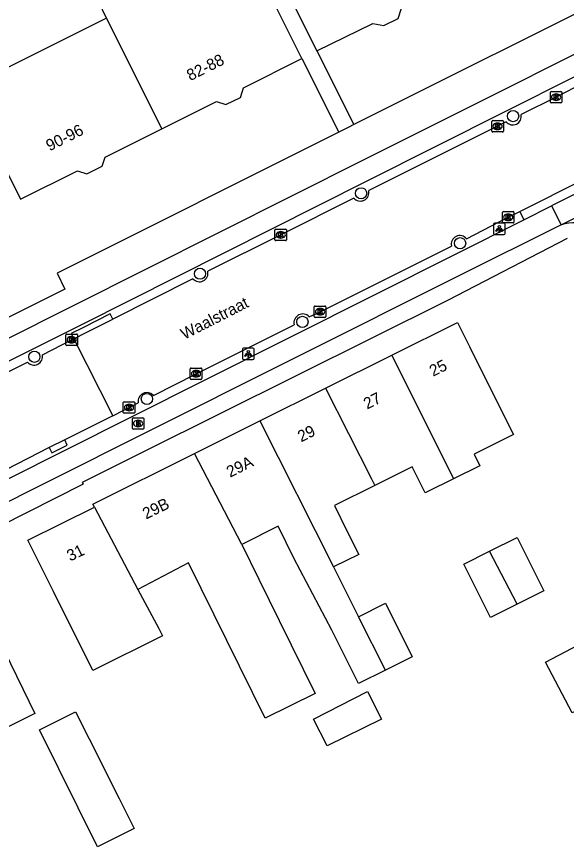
# Model space of a CAD drawing. Extents: x 157321 to 158827, y 386650 to 388532.
# Drawn here: x 157628.3 to 157676.1, y 387630.4 to 387702.9 of the extents above; entities that cross this region are included whole.
import ezdxf

# ---------------------------------------------------------------- set-up
doc = ezdxf.new("R2010")
doc.units = 0
for name, color, linetype in [('IMGEO_Berm_open', 7, 'Continuous'), ('IMGEO_Boom', 7, 'Continuous'), ('IMGEO_Brandkraan', 7, 'Continuous'), ('IMGEO_Fietspad_open', 7, 'Continuous'), ('IMGEO_Kolk', 7, 'Continuous'), ('IMGEO_Lichtpunt', 7, 'Continuous'), ('IMGEO_Openbare_ruimte_label', 7, 'Continuous'), ('IMGEO_Pand', 7, 'Continuous'), ('IMGEO_Pand_nummerreeks', 7, 'Continuous'), ('IMGEO_Rijbaan_lokaal_open', 7, 'Continuous'), ('IMGEO_Voetpad_open', 7, 'Continuous')]:
    doc.layers.add(name, color=color, linetype=linetype)

msp = doc.modelspace()

# ---------------------------------------------------------------- linework, layer by layer
at = {"layer": 'IMGEO_Berm_open'}
for points in [[(157636.639, 387676.533), (157636.413, 387676.983), (157634.094, 387675.811), (157633.035, 387675.276), (157633.267, 387674.819)], [(157631.116, 387665.348), (157631.35, 387664.896), (157632.672, 387665.568), (157632.47, 387666.019)]]:
    msp.add_lwpolyline(points, dxfattribs=at)
at = {"layer": 'IMGEO_Boom'}
for centre in [(157671.491, 387694.214), (157658.257, 387687.49), (157666.873, 387683.142), (157644.238, 387680.488), (157653.156, 387676.295), (157629.818, 387673.254), (157639.614, 387669.579)]:
    msp.add_circle(centre, 0.489, dxfattribs=at)
at = {"layer": 'IMGEO_Brandkraan'}
for p, q in [((157638.347, 387667.015), (157638.347, 387667.867)), ((157638.422, 387667.941), (157639.274, 387667.941)), ((157638.835, 387667.721), (157638.86, 387667.721)), ((157639.348, 387667.867), (157639.348, 387667.015)), ((157638.858, 387667.161), (157638.833, 387667.161)), ((157639.274, 387666.941), (157638.422, 387666.941))]:
    msp.add_line(p, q, dxfattribs=at)
for points in [[(157638.347, 387667.015), (157638.347, 387667.867)], [(157638.422, 387667.941), (157639.274, 387667.941)], [(157639.348, 387667.867), (157639.348, 387667.015)], [(157638.695, 387667.641), (157638.695, 387667.241), (157638.908, 387667.241)], [(157638.926, 387667.641), (157638.695, 387667.641)], [(157638.874, 387667.56), (157638.82, 387667.56), (157638.82, 387667.484)], [(157638.82, 387667.484), (157638.873, 387667.484)], [(157638.882, 387667.408), (157638.82, 387667.408), (157638.82, 387667.327)], [(157638.82, 387667.327), (157638.882, 387667.327)], [(157639.274, 387666.941), (157638.422, 387666.941)]]:
    msp.add_lwpolyline(points, dxfattribs=at)
for centre, radius, start, end in [((157638.424, 387667.865), 0.0765, 91.55205, 178.44795), ((157638.424, 387667.865), 0.0765, 91.55205, 178.44795), ((157639.272, 387667.865), 0.0765, 1.55205, 88.44795), ((157639.272, 387667.865), 0.0765, 1.55205, 88.44795), ((157638.424, 387667.017), 0.0765, 181.55205, 268.44795), ((157638.424, 387667.017), 0.0765, 181.55205, 268.44795), ((157638.875, 387667.522), 0.0379, 267.82845, 90.93552), ((157638.883, 387667.367), 0.0404, 269.87594, 90.50774), ((157638.914, 387667.492), 0.251, 268.66757, 293.53466), ((157638.93, 387667.496), 0.145, 59.4692, 91.53667), ((157638.955, 387667.543), 0.0922, 285.51372, 58.15012), ((157638.96, 387667.351), 0.105, 301.31148, 78.98903), ((157639.272, 387667.017), 0.0765, 271.55205, 358.44795), ((157639.272, 387667.017), 0.0765, 271.55205, 358.44795)]:
    msp.add_arc(centre, radius, start, end, dxfattribs=at)
for centre, major_axis, ratio, start_param, end_param in [((157638.834, 387667.441), (-0.387, 0.002), 0.722429, 4.712389, 7.853982), ((157638.859, 387667.441), (-0.39, 0.002), 0.717154, 1.570796, 4.712389)]:
    msp.add_ellipse(centre, major_axis=major_axis, ratio=ratio, start_param=start_param, end_param=end_param, dxfattribs=at)
at = {"layer": 'IMGEO_Fietspad_open'}
for points in [[(157565.674, 387643.795), (157586.268, 387654.276), (157602.223, 387662.168), (157633.171, 387677.702), (157658.586, 387690.459), (157687.79, 387705.127), (157688.179, 387705.325)], [(157688.948, 387703.712), (157688.853, 387703.664), (157658.704, 387688.508), (157633.965, 387676.076), (157632.808, 387675.494), (157602.899, 387660.494), (157587.041, 387652.538), (157567.394, 387642.71), (157567.399, 387642.417)], [(157674.827, 387686.387), (157675.661, 387684.73)], [(157569.697, 387633.623), (157597.83, 387647.706), (157616.763, 387657.23), (157637.927, 387667.851), (157666.428, 387682.154), (157672.423, 387685.176)], [(157675.661, 387684.73), (157666.647, 387680.247), (157638.747, 387666.244), (157569.945, 387631.713), (157569.232, 387631.358)]]:
    msp.add_lwpolyline(points, dxfattribs=at)
at = {"layer": 'IMGEO_Kolk'}
for p, q in [((157674.731, 387695.437), (157674.731, 387696.289)), ((157674.806, 387696.363), (157675.658, 387696.363)), ((157675.219, 387696.143), (157675.244, 387696.143)), ((157675.732, 387696.289), (157675.732, 387695.437)), ((157675.658, 387695.363), (157674.806, 387695.363)), ((157675.242, 387695.583), (157675.217, 387695.583)), ((157669.64, 387692.903), (157669.64, 387693.755)), ((157669.715, 387693.829), (157670.567, 387693.829)), ((157670.641, 387693.755), (157670.641, 387692.903)), ((157670.151, 387693.049), (157670.126, 387693.049)), ((157670.128, 387693.609), (157670.153, 387693.609)), ((157670.567, 387692.829), (157669.715, 387692.829)), ((157670.565, 387684.978), (157670.565, 387685.83)), ((157670.64, 387685.904), (157671.492, 387685.904)), ((157671.566, 387685.83), (157671.566, 387684.978)), ((157671.076, 387685.124), (157671.051, 387685.124)), ((157671.053, 387685.684), (157671.078, 387685.684)), ((157650.837, 387684.37), (157651.689, 387684.37)), ((157671.492, 387684.904), (157670.64, 387684.904)), ((157650.762, 387683.444), (157650.762, 387684.296)), ((157651.25, 387684.15), (157651.275, 387684.15)), ((157651.763, 387684.296), (157651.763, 387683.444)), ((157651.689, 387683.37), (157650.837, 387683.37)), ((157651.273, 387683.59), (157651.248, 387683.59)), ((157654.187, 387676.747), (157654.187, 387677.599)), ((157654.262, 387677.673), (157655.114, 387677.673)), ((157654.675, 387677.453), (157654.7, 387677.453)), ((157655.188, 387677.599), (157655.188, 387676.747)), ((157655.114, 387676.673), (157654.262, 387676.673)), ((157654.698, 387676.893), (157654.673, 387676.893)), ((157632.559, 387674.306), (157632.559, 387675.158)), ((157632.634, 387675.232), (157633.486, 387675.232)), ((157633.047, 387675.012), (157633.072, 387675.012)), ((157633.56, 387675.158), (157633.56, 387674.306)), ((157633.486, 387674.232), (157632.634, 387674.232)), ((157633.07, 387674.452), (157633.045, 387674.452)), ((157643.391, 387671.348), (157643.391, 387672.2)), ((157643.466, 387672.274), (157644.318, 387672.274)), ((157643.879, 387672.054), (157643.904, 387672.054)), ((157644.392, 387672.2), (157644.392, 387671.348)), ((157643.902, 387671.494), (157643.877, 387671.494)), ((157644.318, 387671.274), (157643.466, 387671.274)), ((157637.558, 387668.408), (157637.558, 387669.26)), ((157637.633, 387669.334), (157638.485, 387669.334)), ((157638.559, 387669.26), (157638.559, 387668.408)), ((157638.069, 387668.554), (157638.044, 387668.554)), ((157638.046, 387669.114), (157638.071, 387669.114)), ((157638.485, 387668.334), (157637.633, 387668.334))]:
    msp.add_line(p, q, dxfattribs=at)
for points in [[(157674.731, 387695.437), (157674.731, 387696.289)], [(157674.806, 387696.363), (157675.658, 387696.363)], [(157675.052, 387696.063), (157675.175, 387696.063), (157675.175, 387695.912), (157675.305, 387696.063), (157675.469, 387696.063), (157675.323, 387695.912), (157675.476, 387695.663), (157675.324, 387695.663), (157675.239, 387695.827), (157675.175, 387695.76), (157675.175, 387695.663), (157675.052, 387695.663), (157675.052, 387696.063)], [(157675.732, 387696.289), (157675.732, 387695.437)], [(157675.658, 387695.363), (157674.806, 387695.363)], [(157669.64, 387692.903), (157669.64, 387693.755)], [(157669.715, 387693.829), (157670.567, 387693.829)], [(157670.641, 387693.755), (157670.641, 387692.903)], [(157669.961, 387693.529), (157670.084, 387693.529), (157670.084, 387693.378), (157670.214, 387693.529), (157670.378, 387693.529), (157670.232, 387693.378), (157670.385, 387693.129), (157670.233, 387693.129), (157670.148, 387693.293), (157670.084, 387693.226), (157670.084, 387693.129), (157669.961, 387693.129), (157669.961, 387693.529)], [(157670.567, 387692.829), (157669.715, 387692.829)], [(157670.565, 387684.978), (157670.565, 387685.83)], [(157670.64, 387685.904), (157671.492, 387685.904)], [(157671.566, 387685.83), (157671.566, 387684.978)], [(157670.886, 387685.604), (157671.009, 387685.604), (157671.009, 387685.453), (157671.139, 387685.604), (157671.303, 387685.604), (157671.157, 387685.453), (157671.31, 387685.204), (157671.158, 387685.204), (157671.073, 387685.368), (157671.009, 387685.301), (157671.009, 387685.204), (157670.886, 387685.204), (157670.886, 387685.604)], [(157650.837, 387684.37), (157651.689, 387684.37)], [(157671.492, 387684.904), (157670.64, 387684.904)], [(157650.762, 387683.444), (157650.762, 387684.296)], [(157651.083, 387684.07), (157651.206, 387684.07), (157651.206, 387683.919), (157651.336, 387684.07), (157651.5, 387684.07), (157651.354, 387683.919), (157651.507, 387683.67), (157651.355, 387683.67), (157651.27, 387683.834), (157651.206, 387683.767), (157651.206, 387683.67), (157651.083, 387683.67), (157651.083, 387684.07)], [(157651.763, 387684.296), (157651.763, 387683.444)], [(157651.689, 387683.37), (157650.837, 387683.37)], [(157654.187, 387676.747), (157654.187, 387677.599)], [(157654.262, 387677.673), (157655.114, 387677.673)], [(157654.508, 387677.373), (157654.631, 387677.373), (157654.631, 387677.222), (157654.761, 387677.373), (157654.925, 387677.373), (157654.779, 387677.222), (157654.932, 387676.973), (157654.78, 387676.973), (157654.695, 387677.137), (157654.631, 387677.07), (157654.631, 387676.973), (157654.508, 387676.973), (157654.508, 387677.373)], [(157655.188, 387677.599), (157655.188, 387676.747)], [(157655.114, 387676.673), (157654.262, 387676.673)], [(157632.559, 387674.306), (157632.559, 387675.158)], [(157632.634, 387675.232), (157633.486, 387675.232)], [(157632.88, 387674.932), (157633.003, 387674.932), (157633.003, 387674.781), (157633.133, 387674.932), (157633.297, 387674.932), (157633.151, 387674.781), (157633.304, 387674.532), (157633.152, 387674.532), (157633.067, 387674.696), (157633.003, 387674.629), (157633.003, 387674.532), (157632.88, 387674.532), (157632.88, 387674.932)], [(157633.56, 387675.158), (157633.56, 387674.306)], [(157633.486, 387674.232), (157632.634, 387674.232)], [(157643.391, 387671.348), (157643.391, 387672.2)], [(157643.466, 387672.274), (157644.318, 387672.274)], [(157644.392, 387672.2), (157644.392, 387671.348)], [(157643.712, 387671.974), (157643.835, 387671.974), (157643.835, 387671.823), (157643.965, 387671.974), (157644.129, 387671.974), (157643.983, 387671.823), (157644.136, 387671.574), (157643.984, 387671.574), (157643.899, 387671.738), (157643.835, 387671.671), (157643.835, 387671.574), (157643.712, 387671.574), (157643.712, 387671.974)], [(157644.318, 387671.274), (157643.466, 387671.274)], [(157637.558, 387668.408), (157637.558, 387669.26)], [(157637.633, 387669.334), (157638.485, 387669.334)], [(157638.559, 387669.26), (157638.559, 387668.408)], [(157637.879, 387669.034), (157638.002, 387669.034), (157638.002, 387668.883), (157638.132, 387669.034), (157638.296, 387669.034), (157638.15, 387668.883), (157638.303, 387668.634), (157638.151, 387668.634), (157638.066, 387668.798), (157638.002, 387668.731), (157638.002, 387668.634), (157637.879, 387668.634), (157637.879, 387669.034)], [(157638.485, 387668.334), (157637.633, 387668.334)]]:
    msp.add_lwpolyline(points, dxfattribs=at)
for centre, start, end in [((157674.808, 387696.287), 91.55205, 178.44795), ((157674.808, 387696.287), 91.55205, 178.44795), ((157675.656, 387696.287), 1.55205, 88.44795), ((157675.656, 387696.287), 1.55205, 88.44795), ((157674.808, 387695.439), 181.55205, 268.44795), ((157674.808, 387695.439), 181.55205, 268.44795), ((157675.656, 387695.439), 271.55205, 358.44795), ((157675.656, 387695.439), 271.55205, 358.44795), ((157669.717, 387693.753), 91.55205, 178.44795), ((157669.717, 387693.753), 91.55205, 178.44795), ((157670.565, 387693.753), 1.55205, 88.44795), ((157670.565, 387693.753), 1.55205, 88.44795), ((157669.717, 387692.905), 181.55205, 268.44795), ((157669.717, 387692.905), 181.55205, 268.44795), ((157670.565, 387692.905), 271.55205, 358.44795), ((157670.565, 387692.905), 271.55205, 358.44795), ((157670.642, 387685.828), 91.55205, 178.44795), ((157670.642, 387685.828), 91.55205, 178.44795), ((157671.49, 387685.828), 1.55205, 88.44795), ((157671.49, 387685.828), 1.55205, 88.44795), ((157650.839, 387684.294), 91.55205, 178.44795), ((157650.839, 387684.294), 91.55205, 178.44795), ((157651.687, 387684.294), 1.55205, 88.44795), ((157651.687, 387684.294), 1.55205, 88.44795), ((157670.642, 387684.98), 181.55205, 268.44795), ((157670.642, 387684.98), 181.55205, 268.44795), ((157671.49, 387684.98), 271.55205, 358.44795), ((157671.49, 387684.98), 271.55205, 358.44795), ((157650.839, 387683.446), 181.55205, 268.44795), ((157650.839, 387683.446), 181.55205, 268.44795), ((157651.687, 387683.446), 271.55205, 358.44795), ((157651.687, 387683.446), 271.55205, 358.44795), ((157654.264, 387677.597), 91.55205, 178.44795), ((157654.264, 387677.597), 91.55205, 178.44795), ((157655.112, 387677.597), 1.55205, 88.44795), ((157655.112, 387677.597), 1.55205, 88.44795), ((157654.264, 387676.749), 181.55205, 268.44795), ((157654.264, 387676.749), 181.55205, 268.44795), ((157655.112, 387676.749), 271.55205, 358.44795), ((157655.112, 387676.749), 271.55205, 358.44795), ((157632.636, 387675.156), 91.55205, 178.44795), ((157632.636, 387675.156), 91.55205, 178.44795), ((157633.484, 387675.156), 1.55205, 88.44795), ((157633.484, 387675.156), 1.55205, 88.44795), ((157632.636, 387674.308), 181.55205, 268.44795), ((157632.636, 387674.308), 181.55205, 268.44795), ((157633.484, 387674.308), 271.55205, 358.44795), ((157633.484, 387674.308), 271.55205, 358.44795), ((157643.468, 387672.198), 91.55205, 178.44795), ((157643.468, 387672.198), 91.55205, 178.44795), ((157644.316, 387672.198), 1.55205, 88.44795), ((157644.316, 387672.198), 1.55205, 88.44795), ((157643.468, 387671.35), 181.55205, 268.44795), ((157643.468, 387671.35), 181.55205, 268.44795), ((157644.316, 387671.35), 271.55205, 358.44795), ((157644.316, 387671.35), 271.55205, 358.44795), ((157637.635, 387669.258), 91.55205, 178.44795), ((157637.635, 387669.258), 91.55205, 178.44795), ((157638.483, 387669.258), 1.55205, 88.44795), ((157638.483, 387669.258), 1.55205, 88.44795), ((157637.635, 387668.41), 181.55205, 268.44795), ((157637.635, 387668.41), 181.55205, 268.44795), ((157638.483, 387668.41), 271.55205, 358.44795), ((157638.483, 387668.41), 271.55205, 358.44795)]:
    msp.add_arc(centre, 0.0765, start, end, dxfattribs=at)
for centre, major_axis, ratio, start_param, end_param in [((157675.218, 387695.863), (-0.387, 0.002), 0.722429, 4.712389, 7.853982), ((157675.243, 387695.863), (-0.39, 0.002), 0.717154, 1.570796, 4.712389), ((157670.127, 387693.329), (-0.387, 0.002), 0.722429, 4.712389, 7.853982), ((157670.152, 387693.329), (-0.39, 0.002), 0.717154, 1.570796, 4.712389), ((157671.052, 387685.404), (-0.387, 0.002), 0.722429, 4.712389, 7.853982), ((157671.077, 387685.404), (-0.39, 0.002), 0.717154, 1.570796, 4.712389), ((157651.249, 387683.87), (-0.387, 0.002), 0.722429, 4.712389, 7.853982), ((157651.274, 387683.87), (-0.39, 0.002), 0.717154, 1.570796, 4.712389), ((157654.674, 387677.173), (-0.387, 0.002), 0.722429, 4.712389, 7.853982), ((157654.699, 387677.173), (-0.39, 0.002), 0.717154, 1.570796, 4.712389), ((157633.046, 387674.732), (-0.387, 0.002), 0.722429, 4.712389, 7.853982), ((157633.071, 387674.732), (-0.39, 0.002), 0.717154, 1.570796, 4.712389), ((157643.878, 387671.774), (-0.387, 0.002), 0.722429, 4.712389, 7.853982), ((157643.903, 387671.774), (-0.39, 0.002), 0.717154, 1.570796, 4.712389), ((157638.045, 387668.834), (-0.387, 0.002), 0.722429, 4.712389, 7.853982), ((157638.07, 387668.834), (-0.39, 0.002), 0.717154, 1.570796, 4.712389)]:
    msp.add_ellipse(centre, major_axis=major_axis, ratio=ratio, start_param=start_param, end_param=end_param, dxfattribs=at)
at = {"layer": 'IMGEO_Lichtpunt'}
for p, q in [((157669.798, 387684.792), (157669.798, 387683.985)), ((157669.798, 387684.792), (157669.798, 387683.985)), ((157670.7, 387684.887), (157669.892, 387684.887)), ((157670.7, 387684.887), (157669.892, 387684.887)), ((157670.794, 387683.985), (157670.794, 387684.792)), ((157670.794, 387683.985), (157670.794, 387684.792)), ((157669.892, 387683.891), (157670.7, 387683.891)), ((157669.892, 387683.891), (157670.7, 387683.891)), ((157647.942, 387673.906), (157647.942, 387673.099)), ((157647.942, 387673.906), (157647.942, 387673.099)), ((157648.844, 387674.001), (157648.036, 387674.001)), ((157648.844, 387674.001), (157648.036, 387674.001)), ((157648.938, 387673.099), (157648.938, 387673.906)), ((157648.938, 387673.099), (157648.938, 387673.906)), ((157648.036, 387673.005), (157648.844, 387673.005)), ((157648.036, 387673.005), (157648.844, 387673.005))]:
    msp.add_line(p, q, dxfattribs=at)
for points in [[(157670.172, 387684.456), (157670.211, 387684.428), (157670.023, 387684.166), (157669.985, 387684.193), (157670.172, 387684.456)], [(157670.274, 387684.408), (157670.321, 387684.408), (157670.321, 387684.086), (157670.274, 387684.086), (157670.274, 387684.408)], [(157670.384, 387684.428), (157670.422, 387684.455), (157670.609, 387684.193), (157670.57, 387684.165), (157670.384, 387684.428)], [(157648.316, 387673.57), (157648.355, 387673.542), (157648.167, 387673.28), (157648.129, 387673.307), (157648.316, 387673.57)], [(157648.418, 387673.522), (157648.465, 387673.522), (157648.465, 387673.2), (157648.418, 387673.2), (157648.418, 387673.522)], [(157648.528, 387673.542), (157648.566, 387673.569), (157648.753, 387673.307), (157648.714, 387673.279), (157648.528, 387673.542)]]:
    msp.add_lwpolyline(points, dxfattribs=at)
for centre in [(157670.297, 387684.59), (157648.441, 387673.704)]:
    msp.add_circle(centre, 0.0994, dxfattribs=at)
for centre, start, end in [((157669.892, 387684.792), 90, 180), ((157669.892, 387684.792), 90, 180), ((157670.7, 387684.792), 0, 90), ((157670.7, 387684.792), 0, 90), ((157669.892, 387683.985), 180, 270), ((157669.892, 387683.985), 180, 270), ((157670.7, 387683.985), 270, 0), ((157670.7, 387683.985), 270, 360), ((157648.036, 387673.906), 90, 180), ((157648.036, 387673.906), 90, 180), ((157648.844, 387673.906), 0, 90), ((157648.844, 387673.906), 0, 90), ((157648.036, 387673.099), 180, 270), ((157648.036, 387673.099), 180, 270), ((157648.844, 387673.099), 270, 0), ((157648.844, 387673.099), 270, 360)]:
    msp.add_arc(centre, 0.0946, start, end, dxfattribs=at)
at = {"layer": 'IMGEO_Pand'}
for points in [[(157649.2, 387710.294), (157649.592, 387709.51), (157654.4, 387699.9)], [(157647.884, 387709.666), (157647.616, 387709.531), (157645.247, 387708.316), (157645.639, 387707.532), (157638.366, 387703.893), (157637.974, 387704.677), (157635.701, 387703.541), (157636.094, 387702.756)], [(157653.107, 387699.225), (157650.87, 387703.697), (157647.884, 387709.666)], [(157654.4, 387699.9), (157659.266, 387702.281), (157660.244, 387702.093), (157661.477, 387702.723), (157661.772, 387703.608), (157666.587, 387706.017)], [(157636.094, 387702.756), (157626.31, 387697.861), (157625.918, 387698.646), (157623.781, 387697.577), (157623.417, 387697.395), (157626.388, 387691.457), (157628.623, 387686.989), (157633.563, 387689.46), (157634.372, 387689.191), (157635.711, 387689.86), (157635.973, 387690.647), (157640.914, 387693.119)], [(157640.914, 387693.119), (157639.655, 387695.638), (157636.094, 387702.756)], [(157640.914, 387693.119), (157645.665, 387695.496), (157646.499, 387695.219), (157647.75, 387695.844), (157648.03, 387696.685), (157653.107, 387699.225)], [(157660.921, 387673.379), (157666.662, 387676.237), (157667.698, 387674.155), (157670.608, 387668.31), (157671.52, 387666.478), (157668.094, 387664.772), (157668.595, 387663.765), (157666.298, 387662.622)], [(157655.172, 387670.517), (157660.921, 387673.379)], [(157660.921, 387673.379), (157666.298, 387662.622)], [(157649.451, 387667.669), (157655.172, 387670.517)], [(157655.172, 387670.517), (157659.154, 387662.624), (157659.443, 387662.051)], [(157643.756, 387664.835), (157649.451, 387667.669)], [(157649.451, 387667.669), (157655.862, 387654.953)], [(157635.046, 387660.153), (157634.908, 387660.43), (157643.756, 387664.835)], [(157647.866, 387656.91), (157643.756, 387664.835)], [(157666.298, 387662.622), (157666.184, 387662.565), (157664.119, 387661.537), (157663.828, 387661.392), (157662.695, 387663.669), (157659.443, 387662.051)], [(157659.443, 387662.051), (157655.931, 387660.302), (157657.059, 387658.035), (157658.051, 387656.042), (157655.862, 387654.953)], [(157638.838, 387652.995), (157640.639, 387649.596), (157640.959, 387648.954), (157634.898, 387645.937), (157631.484, 387652.795), (157629.256, 387657.27), (157635.046, 387660.153)], [(157635.046, 387660.153), (157638.838, 387652.995)], [(157660.373, 387645.958), (157658.043, 387644.791), (157655.712, 387649.446), (157652.414, 387655.723), (157651.043, 387658.496), (157647.866, 387656.91)], [(157647.866, 387656.91), (157649.353, 387653.892), (157651.137, 387650.273), (157654.261, 387643.934), (157649.895, 387641.782), (157643.221, 387655.317), (157638.838, 387652.995)], [(157669.43, 387656.316), (157671.838, 387657.522), (157674.169, 387652.867), (157671.856, 387651.709)], [(157671.856, 387651.709), (157669.532, 387650.545), (157667.201, 387655.2), (157669.43, 387656.316)], [(157671.856, 387651.709), (157669.43, 387656.316)], [(157655.862, 387654.953), (157658.038, 387650.61)], [(157618.227, 387643.983), (157617.874, 387644.682), (157620.348, 387645.932), (157618.814, 387648.967), (157625.02, 387652.104), (157627.217, 387647.613), (157629.869, 387642.19), (157627.077, 387640.78), (157625.805, 387643.297), (157622.623, 387641.689), (157622.943, 387641.056), (157620.362, 387639.752)], [(157658.038, 387650.61), (157660.384, 387651.786), (157662.715, 387647.131), (157660.373, 387645.958)], [(157660.373, 387645.958), (157658.038, 387650.61)], [(157680.713, 387644.405), (157676.62, 387642.252), (157674.316, 387646.645), (157679.568, 387649.4), (157681.826, 387645.097)], [(157654.111, 387641.688), (157658.808, 387644.101), (157660.039, 387641.695), (157655.317, 387639.358), (157654.111, 387641.688)], [(157637.195, 387634.782), (157638.51, 387632.173), (157635.315, 387630.578), (157630.278, 387640.749), (157633.396, 387642.319), (157634.575, 387639.979), (157637.195, 387634.782)]]:
    msp.add_lwpolyline(points, dxfattribs=at)
at = {"layer": 'IMGEO_Rijbaan_lokaal_open'}
for points in [[(157678.384, 387697.475), (157675.232, 387695.861), (157672.183, 387694.339)], [(157672.08, 387685.911), (157688.986, 387694.407)], [(157670.881, 387693.72), (157670.142, 387693.328), (157658.929, 387687.722)], [(157686.319, 387692.175), (157674.827, 387686.387)], [(157675.661, 387684.73), (157687.224, 387690.567)], [(157657.618, 387687.064), (157651.263, 387683.869), (157644.913, 387680.698)], [(157667.432, 387683.529), (157671.065, 387685.405), (157672.08, 387685.911)], [(157672.08, 387685.911), (157672.423, 387685.176)], [(157672.423, 387685.176), (157674.827, 387686.387)], [(157653.747, 387676.741), (157654.687, 387677.174), (157666.121, 387682.899)], [(157643.624, 387680.048), (157636.639, 387676.533)], [(157633.267, 387674.819), (157634.318, 387675.353), (157636.639, 387676.533)], [(157640.178, 387669.894), (157643.892, 387671.775), (157652.428, 387676.043)], [(157630.518, 387673.434), (157633.06, 387674.73), (157633.267, 387674.819)], [(157633.267, 387674.819), (157636.643, 387668.123)], [(157618.813, 387667.595), (157624.77, 387670.564), (157629.208, 387672.795)], [(157636.643, 387668.123), (157637.609, 387668.61), (157638.058, 387668.836), (157638.861, 387669.25)], [(157636.643, 387668.123), (157632.47, 387666.019)], [(157632.47, 387666.019), (157631.116, 387665.348)], [(157631.116, 387665.348), (157626.402, 387662.945)]]:
    msp.add_lwpolyline(points, dxfattribs=at)
for centre, radius, start, end in [((157671.457, 387694.188), 0.742, 219.12054, 11.73438), ((157658.183, 387687.574), 0.761, 222.08976, 11.21502), ((157676.937, 387680.755), 4.175, 70.08277, 107.79383), ((157666.848, 387683.065), 0.746, 38.48914, 192.84401), ((157644.189, 387680.53), 0.743, 220.47396, 13.04663), ((157653.185, 387676.209), 0.774, 43.42471, 192.34987), ((157629.781, 387673.282), 0.752, 220.35723, 11.64774), ((157639.622, 387669.362), 0.769, 43.75256, 188.36379)]:
    msp.add_arc(centre, radius, start, end, dxfattribs=at)
at = {"layer": 'IMGEO_Voetpad_open'}
for points in [[(157682.023, 387705.714), (157657.627, 387693.47)], [(157654.4, 387699.9), (157657.627, 387693.47)], [(157653.107, 387699.225), (157656.318, 387692.814)], [(157657.627, 387693.47), (157657.128, 387693.22), (157656.318, 387692.814)], [(157656.318, 387692.814), (157631.791, 387680.53), (157632.467, 387679.145), (157601.748, 387663.749), (157585.592, 387655.625), (157585.532, 387655.755), (157579.588, 387652.785), (157579.644, 387652.658), (157578.314, 387651.995), (157577.637, 387653.335), (157564.366, 387646.663)], [(157676.207, 387683.552), (157665.792, 387678.165), (157639.374, 387664.995), (157633.991, 387662.311), (157634.079, 387662.144), (157617.129, 387653.586), (157570.984, 387630.438)]]:
    msp.add_lwpolyline(points, dxfattribs=at)

# ---------------------------------------------------------------- texts
at = {"layer": 'IMGEO_Openbare_ruimte_label'}
msp.add_text('Waalstraat', height=1, rotation=27.12877, dxfattribs=at).set_placement((157642.874, 387674.718))
at = {"layer": 'IMGEO_Pand_nummerreeks'}
for s, rotation, p in [('82-88', 26.56232, (157643.388, 387697.253)), ('90-96', 26.61962, (157631.139, 387691.135)), ('25', 26.46492, (157664.516, 387671.504)), ('27', 26.46492, (157658.779, 387668.648)), ('29', 26.46492, (157653.042, 387665.792)), ('29A', 26.46392, (157646.851, 387662.711)), ('29B', 25.98937, (157639.535, 387659.074)), ('31', 25.6857, (157632.934, 387655.412))]:
    msp.add_text(s, height=1, rotation=rotation, dxfattribs=at).set_placement(p)

doc.saveas('drawing.dxf')
